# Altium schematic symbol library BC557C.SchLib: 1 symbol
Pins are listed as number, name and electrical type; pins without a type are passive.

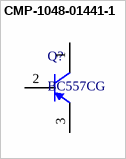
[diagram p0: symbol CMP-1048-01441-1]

## CMP-1048-01441-1
designator Q?, comment BC557CG
Amplifier Transistor, PNP Silicon, 3-Pin TO-92, Pb-Free, Bulk Box; Manufacturer: On Semiconductor; IC Continuous (A): -0.1
footprint ONSC-TO-92-3-29-11 (TO, 3-Leads, Body Dia 4.7mm, Pitch 1.27mm)
pins: 1 C, 2 B, 3 E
